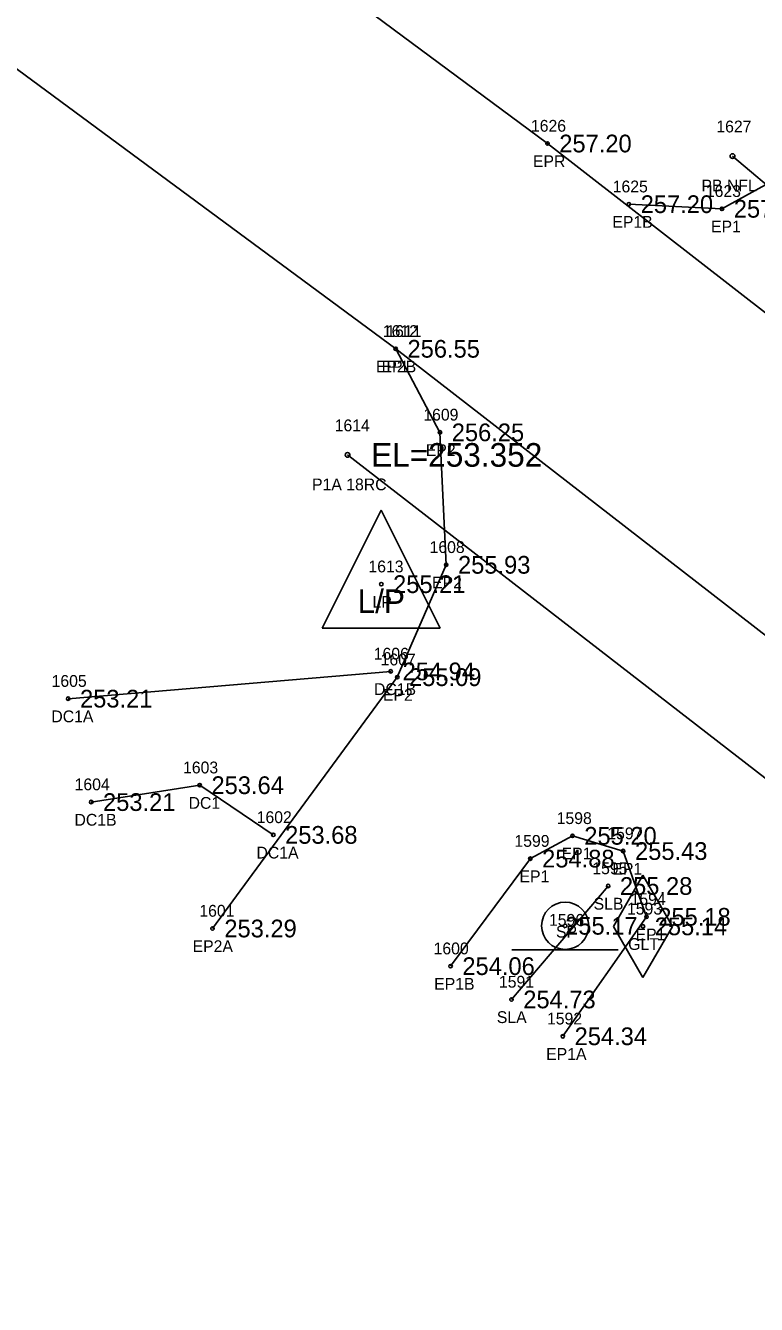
# Model space of a CAD drawing. Extents: x 1961231 to 1962574, y 799865 to 801120.
# Drawn here: x 1961400.7 to 1961462.6, y 800894.4 to 801002.7 of the extents above; entities that cross this region are included whole.
import ezdxf

# ---------------------------------------------------------------- set-up
doc = ezdxf.new("R2010")
doc.units = 0
for name, color, linetype in [('RD_EX_BldgApp', 7, 'Continuous'), ('RD_EX_BldgApp_txCode', 7, 'Continuous'), ('RD_EX_Conc', 7, 'Continuous'), ('RD_EX_Conc_txCode', 7, 'Continuous'), ('RD_EX_DR_Pipe', 7, 'Continuous'), ('RD_EX_DR_Pipe_txCode', 7, 'Continuous'), ('RD_EX_Road', 7, 'Continuous'), ('RD_EX_Road_txCode', 7, 'Continuous'), ('RD_EX_TX_BldgApp_ELEV', 7, 'Continuous'), ('RD_EX_TX_Conc_ELEV', 7, 'Continuous'), ('RD_EX_TX_Road_ELEV', 7, 'Continuous'), ('RD_EX_TX_UT_ELEV', 7, 'Continuous'), ('RD_EX_TX_VEG_ELEV', 7, 'Continuous'), ('RD_EX_UT', 7, 'Continuous'), ('RD_EX_UT_txCode', 7, 'Continuous'), ('RD_EX_VEG', 7, 'Continuous'), ('RD_EX_VEG_txCode', 7, 'Continuous'), ('RD_SMD_Locator', 7, 'Continuous'), ('RD_TX_Pipe_ElevEX', 7, 'Continuous')]:
    doc.layers.add(name, color=color, linetype=linetype)

msp = doc.modelspace()

# ---------------------------------------------------------------- linework, layer by layer
at = {"layer": 'RD_EX_BldgApp'}
msp.add_line((1961441.86, 800924.42), (1961450.86, 800924.42), dxfattribs=at)
msp.add_circle((1961446.38, 800926.45), 2, dxfattribs=at)
at = {"layer": 'RD_EX_Conc'}
msp.add_line((1961404.27, 800945.69), (1961431.6, 800948), dxfattribs=at)
msp.add_lwpolyline([(1961421.65, 800934.15), (1961415.41, 800938.36), (1961406.22, 800936.93)], dxfattribs=at)
at = {"layer": 'RD_EX_DR_Pipe'}
for p, q in [((1961501.48, 800956.87), (1961460.56, 800991.66)), ((1961427.94, 800966.34), (1961492.04, 800916.71))]:
    msp.add_line(p, q, dxfattribs=at)
at = {"layer": 'RD_EX_Road'}
for points in [[(1961735.63, 800762.82), (1961702.92, 800788.52), (1961676.16, 800810.27), (1961651.45, 800830.73), (1961641.14, 800839.02), (1961595.18, 800874.45), (1961552.9, 800907.54), (1961510.92, 800940.49), (1961504.01, 800946.58), (1961476.53, 800968.16), (1961444.88, 800992.72), (1961406.41, 801021.23), (1961370.69, 801045.26)], [(1961722.95, 800745.11), (1961689.13, 800771.93), (1961670.14, 800787.03), (1961660.52, 800795.31), (1961637.49, 800813.67), (1961617.86, 800829), (1961581.48, 800857.91), (1961538.42, 800891.96), (1961505, 800917.96), (1961467.33, 800947.97), (1961432.02, 800975.33), (1961392.71, 801004.33), (1961360.06, 801026.78)], [(1961484.46, 801013.43), (1961472.97, 800998.95), (1961472.49, 800999.38), (1961464.24, 800989.69), (1961459.67, 800987.19), (1961451.78, 800987.58)], [(1961416.5, 800926.22), (1961432.15, 800947.51), (1961436.3, 800957.03), (1961435.77, 800968.25), (1961432.02, 800975.33)], [(1961446.18, 800917.09), (1961453.27, 800927.21), (1961451.3, 800932.78), (1961447, 800934.07), (1961443.43, 800932.14), (1961436.67, 800923.03)]]:
    msp.add_lwpolyline(points, dxfattribs=at)
at = {"layer": 'RD_EX_UT'}
for p, q in [((1961425.8, 800951.66), (1961430.8, 800961.66)), ((1961430.8, 800961.66), (1961435.8, 800951.66)), ((1961425.8, 800951.66), (1961435.8, 800951.66)), ((1961450.47, 800926.4), (1961452.97, 800930.73)), ((1961452.97, 800930.73), (1961455.47, 800926.4)), ((1961450.47, 800926.4), (1961452.97, 800922.07)), ((1961452.97, 800922.07), (1961455.47, 800926.4))]:
    msp.add_line(p, q, dxfattribs=at)
at = {"layer": 'RD_EX_VEG'}
msp.add_line((1961441.83, 800920.21), (1961450.02, 800929.82), dxfattribs=at)
at = {"layer": 'RD_SMD_Locator'}
for centre, radius in [((1961444.88, 800992.72), 0.15), ((1961460.56, 800991.66), 0.2), ((1961451.78, 800987.58), 0.15), ((1961459.67, 800987.19), 0.15), ((1961432.02, 800975.33), 0.15), ((1961432.02, 800975.33), 0.15), ((1961435.77, 800968.25), 0.15), ((1961427.94, 800966.34), 0.2), ((1961436.3, 800957.03), 0.15), ((1961430.8, 800955.39), 0.15), ((1961431.6, 800948), 0.15), ((1961432.15, 800947.51), 0.15), ((1961404.27, 800945.69), 0.15), ((1961415.41, 800938.36), 0.15), ((1961406.22, 800936.93), 0.15), ((1961421.65, 800934.15), 0.15), ((1961447, 800934.07), 0.15), ((1961443.43, 800932.14), 0.15), ((1961451.3, 800932.78), 0.15), ((1961450.02, 800929.82), 0.15), ((1961446.38, 800926.45), 0.15), ((1961452.97, 800926.4), 0.15), ((1961453.27, 800927.21), 0.15), ((1961416.5, 800926.22), 0.15), ((1961436.67, 800923.03), 0.15), ((1961441.83, 800920.21), 0.15), ((1961446.18, 800917.09), 0.15)]:
    msp.add_circle(centre, radius, dxfattribs=at)

# ---------------------------------------------------------------- texts
at = {"layer": 'RD_EX_BldgApp_txCode'}
for s, p in [('1596', (1961445.01, 800926.45)), ('SP', (1961445.6, 800925.45))]:
    msp.add_text(s, height=1, dxfattribs=at).set_placement(p)
at = {"layer": 'RD_EX_Conc_txCode'}
for s, p in [('1606', (1961430.16, 800949)), ('1605', (1961402.86, 800946.69)), ('DC1B', (1961430.18, 800946)), ('DC1A', (1961402.84, 800943.69)), ('1603', (1961414, 800939.36)), ('1604', (1961404.81, 800937.93)), ('DC1', (1961414.47, 800936.36)), ('DC1B', (1961404.8, 800934.93)), ('1602', (1961420.24, 800935.15)), ('DC1A', (1961420.22, 800932.15))]:
    msp.add_text(s, height=1, dxfattribs=at).set_placement(p)
at = {"layer": 'RD_EX_DR_Pipe_txCode'}
for s, p in [('1627', (1961459.19, 800993.66)), ('PB NFL', (1961457.93, 800988.66)), ('1614', (1961426.85, 800968.34)), ('P1A 18RC', (1961424.93, 800963.34))]:
    msp.add_text(s, height=1, dxfattribs=at).set_placement(p)
at = {"layer": 'RD_EX_Road_txCode'}
for s, p in [('1626', (1961443.48, 800993.72)), ('EPR', (1961443.65, 800990.72)), ('1625', (1961450.41, 800988.58)), ('1623', (1961458.3, 800988.19)), ('EP1B', (1961450.38, 800985.58)), ('EP1', (1961458.74, 800985.19)), ('1612', (1961430.93, 800976.33)), ('1611', (1961431.22, 800976.33)), ('EP2B', (1961430.34, 800973.33)), ('EPL', (1961430.82, 800973.33)), ('1609', (1961434.36, 800969.25)), ('EP2', (1961434.57, 800966.25)), ('1608', (1961434.89, 800958.03)), ('EP2', (1961435.1, 800955.03)), ('1607', (1961430.74, 800948.51)), ('EP2', (1961430.94, 800945.51)), ('1598', (1961445.66, 800935.07)), ('1599', (1961442.08, 800933.14)), ('1597', (1961449.95, 800933.78)), ('EP1', (1961446.08, 800932.07)), ('EP1', (1961442.51, 800930.14)), ('EP1', (1961450.38, 800930.78)), ('1594', (1961451.92, 800928.21)), ('1601', (1961415.38, 800927.22)), ('EP1', (1961452.35, 800925.21)), ('EP2A', (1961414.81, 800924.22)), ('1600', (1961435.23, 800924.03)), ('EP1B', (1961435.28, 800921.03)), ('1592', (1961444.84, 800918.09)), ('EP1A', (1961444.77, 800915.09))]:
    msp.add_text(s, height=1, dxfattribs=at).set_placement(p)
at = {"layer": 'RD_EX_TX_BldgApp_ELEV'}
msp.add_text('255.17', height=1.5, dxfattribs=at).set_placement((1961446.38, 800925.7))
at = {"layer": 'RD_EX_TX_Conc_ELEV'}
for s, p in [('254.94', (1961432.6, 800947.25)), ('253.21', (1961405.27, 800944.94)), ('253.64', (1961416.41, 800937.61)), ('253.21', (1961407.22, 800936.18)), ('253.68', (1961422.65, 800933.4))]:
    msp.add_text(s, height=1.5, dxfattribs=at).set_placement(p)
at = {"layer": 'RD_EX_TX_Road_ELEV'}
for s, p in [('257.20', (1961445.88, 800991.97)), ('257.20', (1961452.78, 800986.83)), ('257.19', (1961460.67, 800986.44)), ('256.55', (1961433.02, 800974.58)), ('256.55', (1961433.02, 800974.58)), ('256.25', (1961436.77, 800967.5)), ('255.93', (1961437.3, 800956.28)), ('255.09', (1961433.15, 800946.76)), ('255.20', (1961448, 800933.32)), ('255.43', (1961452.3, 800932.03)), ('254.88', (1961444.43, 800931.39)), ('255.18', (1961454.27, 800926.46)), ('253.29', (1961417.5, 800925.47)), ('254.06', (1961437.67, 800922.28)), ('254.34', (1961447.18, 800916.34))]:
    msp.add_text(s, height=1.5, dxfattribs=at).set_placement(p)
at = {"layer": 'RD_EX_TX_UT_ELEV'}
for s, p in [('255.21', (1961431.8, 800954.64)), ('255.14', (1961453.97, 800925.65))]:
    msp.add_text(s, height=1.5, dxfattribs=at).set_placement(p)
at = {"layer": 'RD_EX_TX_VEG_ELEV'}
for s, p in [('255.28', (1961451.02, 800929.07)), ('254.73', (1961442.83, 800919.46))]:
    msp.add_text(s, height=1.5, dxfattribs=at).set_placement(p)
at = {"layer": 'RD_EX_UT'}
msp.add_text('L/P', height=2, dxfattribs=at).set_placement((1961428.79, 800952.94))
at = {"layer": 'RD_EX_UT_txCode'}
for s, p in [('1613', (1961429.71, 800956.39)), ('LP', (1961430.05, 800953.39)), ('1593', (1961451.62, 800927.4)), ('GLT', (1961451.72, 800924.4))]:
    msp.add_text(s, height=1, dxfattribs=at).set_placement(p)
at = {"layer": 'RD_EX_VEG_txCode'}
for s, p in [('1595', (1961448.68, 800930.82)), ('SLB', (1961448.79, 800927.82)), ('1591', (1961440.77, 800921.21)), ('SLA', (1961440.59, 800918.21))]:
    msp.add_text(s, height=1, dxfattribs=at).set_placement(p)
at = {"layer": 'RD_TX_Pipe_ElevEX'}
msp.add_text('EL=253.352', height=2, dxfattribs=at).set_placement((1961429.94, 800965.34))

doc.saveas('drawing.dxf')
